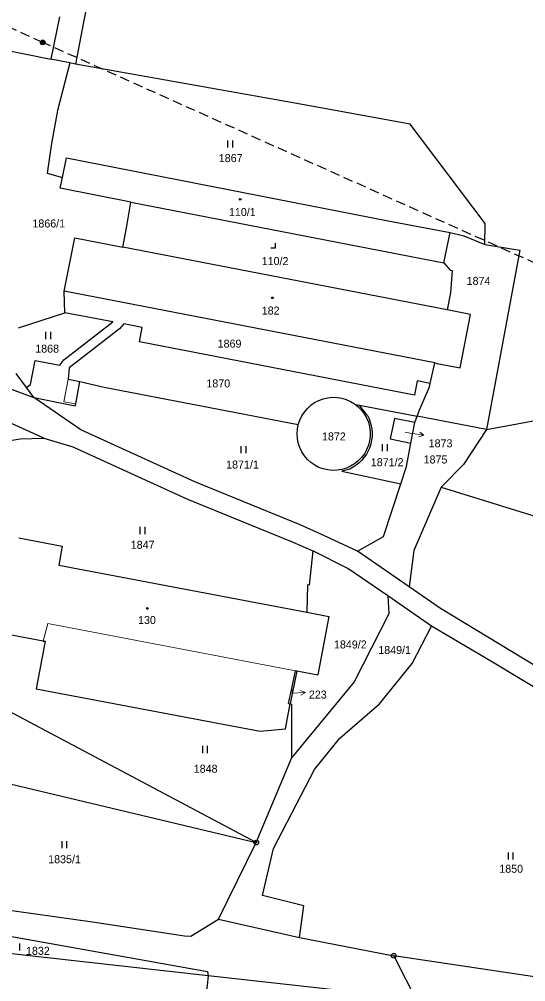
# Model space of a CAD drawing. Extents: x -601131 to -597152, y -1058536 to -1055911.
# Drawn here: x -599173.9 to -599066.3, y -1057066.1 to -1056861.6 of the extents above; entities that cross this region are included whole.
import ezdxf
from ezdxf.enums import TextEntityAlignment as Align

# ---------------------------------------------------------------- set-up
doc = ezdxf.new("R2010")
doc.units = 0
doc.header["$LTSCALE"] = 0.68
doc.linetypes.add('MEDIUM_DASHED', pattern=[4.5, 3, -1.5])
for name, color, linetype, lineweight in [('1', 7, 'Continuous', 25), ('3', 7, 'Continuous', 25), ('4', 7, 'Continuous', 13), ('5', 7, 'Continuous', 25), ('6', 7, 'Continuous', 25), ('7', 7, 'Continuous', 13), ('8', 7, 'Continuous', 25)]:
    doc.layers.add(name, color=color, linetype=linetype, lineweight=lineweight)
doc.layers.add('2', color=7, linetype='Continuous')

msp = doc.modelspace()

# ---------------------------------------------------------------- linework, layer by layer
at = {"layer": '1'}
for p, q in [((-599150.14, -1056811.27), (-599160.28, -1056862.26)), ((-599165.35, -1056861.13), (-599167.19, -1056870.09)), ((-599160.28, -1056862.26), (-599161.97, -1056871.15)), ((-599178.14, -1056867.87), (-599167.19, -1056870.09)), ((-599163.14, -1056870.91), (-599167.19, -1056870.09)), ((-599163.14, -1056870.91), (-599165.76, -1056880.99)), ((-599161.97, -1056871.15), (-599163.14, -1056870.91)), ((-599114.13, -1056879.68), (-599161.97, -1056871.15)), ((-599090.84, -1056883.93), (-599114.13, -1056879.68)), ((-599074.87, -1056905.02), (-599090.84, -1056883.93)), ((-599164.72, -1056895.26), (-599163.85, -1056891.06)), ((-599163.85, -1056891.06), (-599095.5, -1056904.43)), ((-599168, -1056894.29), (-599164.72, -1056895.26)), ((-599165.19, -1056897.54), (-599164.72, -1056895.26)), ((-599150.17, -1056900.46), (-599165.19, -1056897.54)), ((-599151.02, -1056905.61), (-599150.17, -1056900.46)), ((-599150.17, -1056900.46), (-599083.71, -1056913.4)), ((-599095.5, -1056904.43), (-599082.32, -1056906.91)), ((-599151.88, -1056910.04), (-599151.02, -1056905.61)), ((-599083.71, -1056913.4), (-599082.32, -1056906.91)), ((-599082.32, -1056906.91), (-599079.44, -1056907.63)), ((-599074.96, -1056909.47), (-599074.87, -1056905.02)), ((-599164.35, -1056919.37), (-599162.12, -1056908.06)), ((-599162.12, -1056908.06), (-599151.88, -1056910.04)), ((-599079.44, -1056907.63), (-599074.96, -1056909.47)), ((-599082.95, -1056923.38), (-599151.88, -1056910.04)), ((-599074.96, -1056909.47), (-599067.49, -1056910.68)), ((-599067.49, -1056910.68), (-599074.64, -1056948.81)), ((-599083.71, -1056913.4), (-599082.3, -1056914.94)), ((-599082.3, -1056914.94), (-599081.91, -1056914.99)), ((-599081.91, -1056914.99), (-599082.26, -1056919.78)), ((-599085.6, -1056934.63), (-599164.35, -1056919.37)), ((-599164.24, -1056923.98), (-599164.35, -1056919.37)), ((-599082.26, -1056919.78), (-599082.95, -1056923.38)), ((-599077.98, -1056924.34), (-599082.95, -1056923.38)), ((-599174.1, -1056927.16), (-599164.24, -1056923.98)), ((-599154, -1056925.92), (-599164.24, -1056923.98)), ((-599080.19, -1056935.68), (-599077.98, -1056924.34)), ((-599164.43, -1056933.99), (-599154, -1056925.92)), ((-599152.63, -1056927.41), (-599163.32, -1056935.68)), ((-599151.71, -1056926.35), (-599152.63, -1056927.41)), ((-599147.79, -1056927.14), (-599151.71, -1056926.35)), ((-599148.35, -1056930.14), (-599147.79, -1056927.14)), ((-599089.88, -1056941.5), (-599148.35, -1056930.14)), ((-599074.64, -1056948.81), (-598986.49, -1056932.15)), ((-599171.5, -1056939.21), (-599170.55, -1056934.11)), ((-599170.55, -1056934.11), (-599165.28, -1056935.09)), ((-599165.28, -1056935.09), (-599164.43, -1056933.99)), ((-599163.32, -1056935.68), (-599163.54, -1056938.1)), ((-599086.58, -1056938.98), (-599085.6, -1056934.63)), ((-599085.6, -1056934.63), (-599085.08, -1056934.73)), ((-599085.08, -1056934.73), (-599080.19, -1056935.68)), ((-599172.34, -1056939.83), (-599174.55, -1056936.89)), ((-599168.67, -1056950.62), (-599193.16, -1056939.63)), ((-599172.34, -1056939.83), (-599171.5, -1056939.21)), ((-599163.54, -1056938.1), (-599161.04, -1056938.6)), ((-599161.89, -1056943.31), (-599161.04, -1056938.6)), ((-599161.04, -1056938.6), (-599155.89, -1056939.77)), ((-599155.89, -1056939.77), (-599114.61, -1056947.75)), ((-599089.37, -1056938.42), (-599089.88, -1056941.5)), ((-599086.58, -1056938.98), (-599089.37, -1056938.42)), ((-599088.78, -1056944.5), (-599086.7, -1056939.71)), ((-599086.7, -1056939.71), (-599086.58, -1056938.98)), ((-599160.82, -1056948.89), (-599170.81, -1056942.02)), ((-599170.81, -1056942.02), (-599162.05, -1056943.73)), ((-599162.05, -1056943.73), (-599161.89, -1056943.31)), ((-599112.68, -1056944.31), (-599111.94, -1056943.64)), ((-599111.94, -1056943.64), (-599111.13, -1056943.07)), ((-599111.13, -1056943.07), (-599110.24, -1056942.61)), ((-599110.24, -1056942.61), (-599109.31, -1056942.26)), ((-599109.31, -1056942.26), (-599108.34, -1056942.04)), ((-599108.34, -1056942.04), (-599107.35, -1056941.94)), ((-599107.35, -1056941.94), (-599106.35, -1056941.97)), ((-599106.35, -1056941.97), (-599105.37, -1056942.13)), ((-599105.37, -1056942.13), (-599104.41, -1056942.41)), ((-599104.41, -1056942.41), (-599103.5, -1056942.81)), ((-599103.5, -1056942.81), (-599102.65, -1056943.33)), ((-599102.65, -1056943.33), (-599102.47, -1056943.46)), ((-599102.47, -1056943.46), (-599101.87, -1056943.95)), ((-599102.47, -1056943.46), (-599101.62, -1056943.62)), ((-599101.62, -1056943.62), (-599089.33, -1056945.99)), ((-599114.3, -1056946.8), (-599113.87, -1056945.91)), ((-599113.87, -1056945.91), (-599113.32, -1056945.07)), ((-599113.32, -1056945.07), (-599112.68, -1056944.31)), ((-599101.87, -1056943.95), (-599101.17, -1056944.66)), ((-599101.17, -1056944.66), (-599100.58, -1056945.46)), ((-599100.58, -1056945.46), (-599100.09, -1056946.33)), ((-599089.33, -1056945.99), (-599088.78, -1056944.5)), ((-599114.8, -1056948.73), (-599114.61, -1056947.75)), ((-599114.61, -1056947.75), (-599114.3, -1056946.8)), ((-599100.09, -1056946.33), (-599099.71, -1056947.25)), ((-599099.71, -1056947.25), (-599099.46, -1056948.22)), ((-599094.17, -1056946.44), (-599095.07, -1056950.79)), ((-599089.81, -1056947.3), (-599094.17, -1056946.44)), ((-599090.69, -1056951.72), (-599089.81, -1056947.3)), ((-599089.81, -1056947.3), (-599089.33, -1056945.99)), ((-599074.64, -1056948.81), (-599089.33, -1056945.99)), ((-599136.59, -1056959.89), (-599160.82, -1056948.89)), ((-599114.86, -1056949.72), (-599114.8, -1056948.73)), ((-599114.8, -1056950.72), (-599114.86, -1056949.72)), ((-599099.46, -1056948.22), (-599099.33, -1056949.2)), ((-599099.33, -1056949.2), (-599099.33, -1056950.2)), ((-599074.64, -1056948.81), (-599079.51, -1056956.23)), ((-599177.14, -1056951.36), (-599173.7, -1056950.75)), ((-599173.7, -1056950.75), (-599168.67, -1056950.62)), ((-599168.67, -1056950.62), (-599162.53, -1056952.5)), ((-599114.61, -1056951.69), (-599114.8, -1056950.72)), ((-599114.29, -1056952.64), (-599114.61, -1056951.69)), ((-599099.45, -1056951.19), (-599099.71, -1056952.15)), ((-599099.33, -1056950.2), (-599099.45, -1056951.19)), ((-599095.07, -1056950.79), (-599090.69, -1056951.72)), ((-599091.63, -1056956.67), (-599090.69, -1056951.72)), ((-599162.53, -1056952.5), (-599138.16, -1056963.57)), ((-599113.86, -1056953.54), (-599114.29, -1056952.64)), ((-599113.31, -1056954.37), (-599113.86, -1056953.54)), ((-599100.57, -1056953.94), (-599101.16, -1056954.74)), ((-599100.08, -1056953.08), (-599100.57, -1056953.94)), ((-599099.71, -1056952.15), (-599100.08, -1056953.08)), ((-599112.66, -1056955.13), (-599113.31, -1056954.37)), ((-599111.93, -1056955.8), (-599112.66, -1056955.13)), ((-599111.11, -1056956.37), (-599111.93, -1056955.8)), ((-599102.63, -1056956.08), (-599103.48, -1056956.6)), ((-599101.85, -1056955.46), (-599102.63, -1056956.08)), ((-599101.16, -1056954.74), (-599101.85, -1056955.46)), ((-599110.22, -1056956.83), (-599111.11, -1056956.37)), ((-599109.29, -1056957.17), (-599110.22, -1056956.83)), ((-599108.32, -1056957.39), (-599109.29, -1056957.17)), ((-599107.32, -1056957.48), (-599108.32, -1056957.39)), ((-599106.33, -1056957.45), (-599107.32, -1056957.48)), ((-599105.35, -1056957.29), (-599106.33, -1056957.45)), ((-599104.39, -1056957), (-599105.35, -1056957.29)), ((-599103.48, -1056956.6), (-599104.39, -1056957)), ((-599092.82, -1056960.3), (-599091.63, -1056956.67)), ((-599079.51, -1056956.23), (-599084.24, -1056961.01)), ((-599114.2, -1056969.01), (-599136.59, -1056959.89)), ((-599096.5, -1056971.55), (-599092.82, -1056960.3)), ((-599084.24, -1056961.01), (-599090.05, -1056974.49)), ((-599084.24, -1056961.01), (-599019.53, -1056981.2)), ((-599138.16, -1056963.57), (-599115.91, -1056972.63)), ((-599109.94, -1056970.94), (-599114.2, -1056969.01)), ((-599174.02, -1056971.83), (-599164.76, -1056973.61)), ((-599102.03, -1056974.63), (-599109.94, -1056970.94)), ((-599102.03, -1056974.63), (-599096.5, -1056971.55)), ((-599164.76, -1056973.61), (-599165.49, -1056977.58)), ((-599115.91, -1056972.63), (-599111.54, -1056974.6)), ((-599090.05, -1056974.49), (-599091.05, -1056982.2)), ((-599111.54, -1056974.6), (-599112.3, -1056981.87)), ((-599104.06, -1056978.3), (-599111.54, -1056974.6)), ((-599091.05, -1056982.2), (-599102.03, -1056974.63)), ((-599165.49, -1056977.58), (-599112.82, -1056987.62)), ((-599095.6, -1056984.14), (-599104.06, -1056978.3)), ((-599112.62, -1056981.8), (-599112.82, -1056987.62)), ((-599112.3, -1056981.87), (-599112.62, -1056981.8)), ((-599084.38, -1056986.79), (-599091.05, -1056982.2)), ((-599086.3, -1056990.56), (-599095.6, -1056984.14)), ((-599052.46, -1057006.17), (-599084.38, -1056986.79)), ((-599112.82, -1056987.62), (-599108.09, -1056988.52)), ((-599108.09, -1056988.52), (-599110.49, -1057000.93)), ((-599090.42, -1056998.52), (-599086.3, -1056990.56)), ((-599073.32, -1056998.2), (-599086.3, -1056990.56)), ((-599168.84, -1056993.77), (-599177.86, -1056992.06)), ((-599168.39, -1056993.74), (-599170.29, -1057003.9)), ((-599168.84, -1056993.77), (-599168.39, -1056993.74)), ((-599097.38, -1057007.08), (-599090.42, -1056998.52)), ((-599054.5, -1057009.61), (-599073.32, -1056998.2)), ((-599114.94, -1057000.09), (-599116.3, -1057007.09)), ((-599115.93, -1057003.45), (-599115.18, -1057000.04)), ((-599115.18, -1057000.04), (-599114.94, -1057000.09)), ((-599114.94, -1057000.09), (-599110.49, -1057000.93)), ((-599123.54, -1057036.57), (-599189.85, -1057001.36)), ((-599170.29, -1057003.9), (-599122.7, -1057012.89)), ((-599116.66, -1057007.02), (-599115.93, -1057003.45)), ((-599117.34, -1057012.41), (-599116.3, -1057007.09)), ((-599115.96, -1057018.51), (-599116.01, -1057007.15)), ((-599105.77, -1057014.4), (-599097.38, -1057007.08)), ((-599122.7, -1057012.89), (-599117.34, -1057012.41)), ((-599111.14, -1057021), (-599105.77, -1057014.4)), ((-599195.31, -1057019.42), (-599123.54, -1057036.57)), ((-599123.54, -1057036.57), (-599115.96, -1057018.51)), ((-599119.9, -1057037.83), (-599111.14, -1057021)), ((-599131.6, -1057052.86), (-599123.54, -1057036.57)), ((-599122.2, -1057047.77), (-599119.9, -1057037.83)), ((-599113.4, -1057049.98), (-599122.2, -1057047.77)), ((-599189.96, -1057048.94), (-599158.35, -1057053.42)), ((-599114.33, -1057056.72), (-599113.4, -1057049.98)), ((-599158.35, -1057053.42), (-599138.82, -1057056.39)), ((-599137.48, -1057056.43), (-599131.6, -1057052.86)), ((-599131.6, -1057052.86), (-599114.33, -1057056.72)), ((-599177.13, -1057056.24), (-599133.89, -1057063.93)), ((-599138.82, -1057056.39), (-599137.48, -1057056.43)), ((-599114.33, -1057056.72), (-599094.31, -1057060.61)), ((-599045.18, -1057068), (-599094.31, -1057060.61)), ((-599094.31, -1057060.61), (-599089.27, -1057070.52)), ((-599133.89, -1057063.93), (-599133.73, -1057064.9)), ((-599133.73, -1057064.9), (-599134.46, -1057071.44)), ((-599105.08, -1057068.07), (-599133.73, -1057064.9))]:
    msp.add_line(p, q, dxfattribs=at)
for points in [[(-599165.76, -1056880.99), (-599167.06, -1056888.04), (-599168, -1056894.29)], [(-599194.32, -1056933.34), (-599170.81, -1056942.02), (-599172.34, -1056939.83)], [(-599099.91, -1056945.8), (-599101.46, -1056943.83), (-599101.62, -1056943.62)], [(-599099.91, -1056945.8), (-599099.572, -1056946.501), (-599099.302, -1056947.231), (-599099.101, -1056947.983), (-599098.973, -1056948.751), (-599098.918, -1056949.527), (-599098.937, -1056950.305), (-599099.029, -1056951.078), (-599099.194, -1056951.838), (-599099.43, -1056952.58)], [(-599099.43, -1056952.58), (-599099.755, -1056953.308), (-599100.145, -1056954.004), (-599100.596, -1056954.662), (-599101.105, -1056955.276), (-599101.668, -1056955.841), (-599102.28, -1056956.353), (-599102.936, -1056956.807), (-599103.63, -1056957.2)], [(-599103.63, -1056957.2), (-599105.36, -1056957.66), (-599092.82, -1056960.3)], [(-599095.6, -1056984.14), (-599095.37, -1056987.96), (-599102.74, -1057002.4), (-599115.96, -1057018.51)], [(-599116.66, -1057007.02), (-599116.3, -1057007.09), (-599116.01, -1057007.15)], [(-599133.73, -1057064.9), (-599177.41, -1057060), (-599177.13, -1057056.24)]]:
    msp.add_lwpolyline(points, dxfattribs=at)
at = {"layer": '3'}
for p, q in [((-599129.551, -1056888.88), (-599129.551, -1056887.38)), ((-599128.55, -1056888.88), (-599128.55, -1056887.38)), ((-599168.231, -1056929.57), (-599168.231, -1056928.07)), ((-599167.23, -1056929.57), (-599167.23, -1056928.07)), ((-599096.681, -1056953.38), (-599096.681, -1056951.88)), ((-599095.68, -1056953.38), (-599095.68, -1056951.88)), ((-599126.721, -1056953.82), (-599126.721, -1056952.32)), ((-599125.72, -1056953.82), (-599125.72, -1056952.32)), ((-599148.181, -1056971), (-599148.181, -1056969.5)), ((-599147.18, -1056971), (-599147.18, -1056969.5)), ((-599134.931, -1057017.53), (-599134.931, -1057016.03)), ((-599133.93, -1057017.53), (-599133.93, -1057016.03)), ((-599164.811, -1057037.75), (-599164.811, -1057036.25)), ((-599163.81, -1057037.75), (-599163.81, -1057036.25)), ((-599069.951, -1057040.18), (-599069.951, -1057038.68)), ((-599068.95, -1057040.18), (-599068.95, -1057038.68)), ((-599173.81, -1057059.47), (-599173.81, -1057057.97))]:
    msp.add_line(p, q, dxfattribs=at)
msp.add_lwpolyline([(-599120.441, -1056910.2), (-599119.44, -1056910.2), (-599119.44, -1056909.2)], dxfattribs=at)
at = {"layer": '4'}
for p, q in [((-599164.46, -1056942.93), (-599163.54, -1056938.1)), ((-599161.89, -1056943.31), (-599164.46, -1056942.93)), ((-599168.84, -1056993.77), (-599167.87, -1056990.04)), ((-599167.87, -1056990.04), (-599115.18, -1057000.04))]:
    msp.add_line(p, q, dxfattribs=at)
at = {"layer": '5'}
for centre, radius in [((-599126.9468, -1056899.8692), 0.175), ((-599120.0868, -1056920.8092), 0.175), ((-599146.6868, -1056986.8192), 0.175), ((-599115.9146, -1057004.2294), 0.1172)]:
    msp.add_circle(centre, radius, dxfattribs=at)
at = {"layer": '6', "linetype": 'MEDIUM_DASHED'}
for p, q in [((-599168.92, -1056866.53), (-599311.59, -1056802.59)), ((-599010.92, -1056937.38), (-599168.92, -1056866.53))]:
    msp.add_line(p, q, dxfattribs=at)
at = {"layer": '6'}
for radius in [0.5, 0.4, 0.3, 0.2, 0.1]:
    msp.add_circle((-599168.9234, -1056866.5299), radius, dxfattribs=at)
at = {"layer": '7'}
for p, q in [((-599087.896, -1056950.019), (-599088.807, -1056949.368)), ((-599113.111, -1057004.685), (-599114.129, -1057004.22))]:
    msp.add_line(p, q, dxfattribs=at)
for points in [[(-599091.91, -1056949.38), (-599090.86, -1056949.55), (-599087.896, -1056950.019), (-599088.963, -1056950.357)], [(-599116.11, -1057004.79), (-599113.111, -1057004.685), (-599114.094, -1057005.221)]]:
    msp.add_lwpolyline(points, dxfattribs=at)
at = {"layer": '8'}
for centre, radius in [((-599123.54, -1057036.5699), 0.5), ((-599123.54, -1057036.5699), 0.0303), ((-599094.31, -1057060.6099), 0.5), ((-599094.31, -1057060.6099), 0.0303)]:
    msp.add_circle(centre, radius, dxfattribs=at)

# ---------------------------------------------------------------- texts
at = {"layer": '2'}
for s, p in [('1867', (-599128.98, -1056891.972)), ('110/1', (-599126.51, -1056903.432)), ('1866/1', (-599167.64, -1056905.865)), ('110/2', (-599119.54, -1056913.852)), ('1874', (-599076.3, -1056918.062)), ('182', (-599120.479, -1056924.362)), ('1868', (-599167.99, -1056932.462)), ('1869', (-599129.22, -1056931.392)), ('1870', (-599131.61, -1056939.842)), ('1872', (-599107.04, -1056951.112)), ('1871/1', (-599126.47, -1056957.084)), ('1871/2', (-599095.72, -1056956.584)), ('1875', (-599085.45, -1056956.012)), ('1847', (-599147.69, -1056974.142)), ('130', (-599146.769, -1056990.122)), ('1849/2', (-599103.55, -1056995.314)), ('1849/1', (-599094.13, -1056996.495)), ('1848', (-599134.3, -1057021.722)), ('1835/1', (-599164.29, -1057040.945)), ('1850', (-599069.37, -1057042.972)), ('1832', (-599169.95, -1057060.412))]:
    msp.add_text(s, height=1.7, dxfattribs=at).set_placement(p, align=Align.CENTER)
for s, p in [('1873', (-599086.9, -1056952.575)), ('223', (-599112.36, -1057005.962))]:
    msp.add_text(s, height=1.7, dxfattribs=at).set_placement(p)

doc.saveas('drawing.dxf')
